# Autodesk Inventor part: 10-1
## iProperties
Author: Administrator
Created: 2001-02
Part Number: 10-1
Document SubType Name: Modeling
Designer: Administrator
Control State: 0
Master: False
Checked Out: False
PropertySet Name: Design Tracking Control
Shininess: 20.0
PropertySet Name: _Private Model Information
Density: 0.0
Volumn: 0.0
Area: 0.0
PropertySet Name: Model Information
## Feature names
1. Extrusion1
2. Extrusion2
3. Extrusion3
4. Fillet1
5. Hole1
